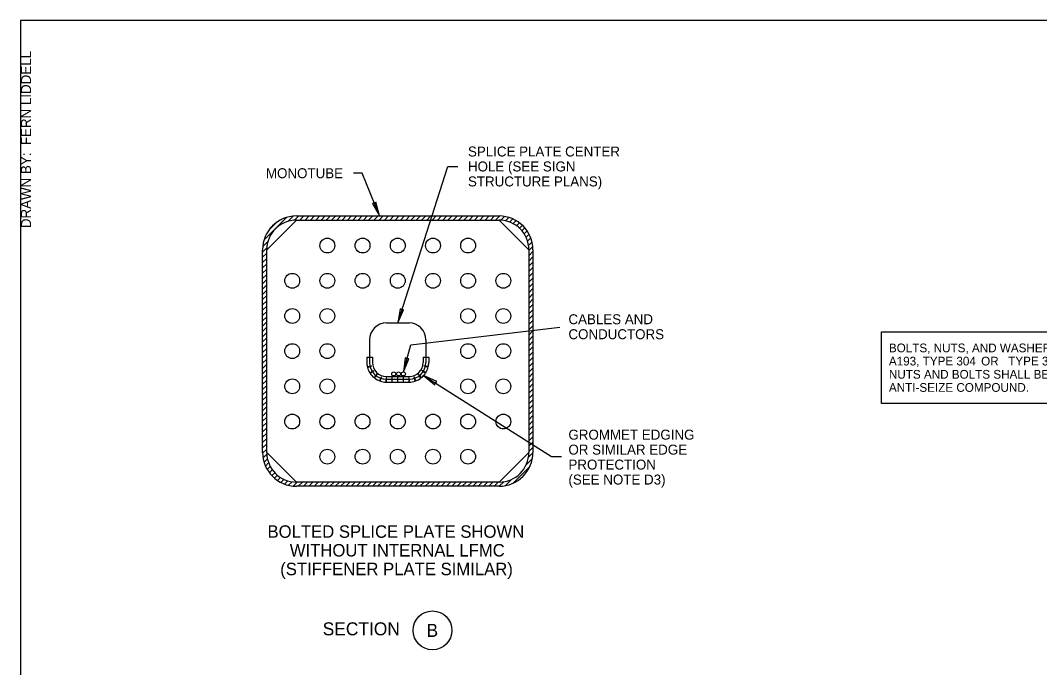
# Model space of a CAD drawing. Extents: x 99862 to 103680, y 99470 to 105076.
# Drawn here: x 99862 to 101496, y 104038 to 105076 of the extents above; entities that cross this region are included whole.
import ezdxf

# ---------------------------------------------------------------- set-up
doc = ezdxf.new("R2010")
doc.units = 0
for name, color, linetype in [('Level 1', 7, 'Continuous'), ('Level 12', 7, 'Continuous'), ('Level 15', 7, 'Continuous'), ('Level 2', 7, 'Continuous'), ('Level 20', 7, 'Continuous'), ('Level 3', 7, 'Continuous'), ('Level 62', 7, 'Continuous'), ('Level 9', 7, 'Continuous')]:
    doc.layers.add(name, color=color, linetype=linetype)

msp = doc.modelspace()

# ---------------------------------------------------------------- linework, layer by layer
at = {"layer": 'Level 1'}
msp.add_lwpolyline([(99862, 102999.5), (103151, 102999.5), (103151, 105075.5), (99862, 105075.5)], close=True, dxfattribs=at)
at = {"layer": 'Level 12'}
for p, q in [((100252.7, 104723.3), (100288.9, 104759.5)), ((100257, 104707.6), (100304.5, 104755.2)), ((100261.8, 104740.9), (100271.3, 104750.4)), ((100291.2, 104753.3), (100299.4, 104761.5)), ((100301.5, 104755.1), (100308.2, 104761.8)), ((100304.5, 104761.8), (100629.6, 104761.8)), ((100304.5, 104755.2), (100629.6, 104755.2)), ((100310.1, 104755.2), (100316.6, 104761.8)), ((100318.5, 104755.2), (100325.1, 104761.8)), ((100327, 104755.2), (100333.6, 104761.8)), ((100335.5, 104755.2), (100342.1, 104761.8)), ((100344, 104755.2), (100350.6, 104761.8)), ((100352.5, 104755.2), (100359.1, 104761.8)), ((100361, 104755.2), (100367.5, 104761.8)), ((100369.5, 104755.2), (100376, 104761.8)), ((100377.9, 104755.2), (100384.5, 104761.8)), ((100386.4, 104755.2), (100393, 104761.8)), ((100394.9, 104755.2), (100401.5, 104761.8)), ((100403.4, 104755.2), (100410, 104761.8)), ((100411.9, 104755.2), (100418.5, 104761.8)), ((100420.4, 104755.2), (100426.9, 104761.8)), ((100428.9, 104755.2), (100435.4, 104761.8)), ((100437.3, 104755.2), (100443.9, 104761.8)), ((100445.8, 104755.2), (100452.4, 104761.8)), ((100454.3, 104755.2), (100460.9, 104761.8)), ((100462.8, 104755.2), (100469.4, 104761.8)), ((100471.3, 104755.2), (100477.9, 104761.8)), ((100479.8, 104755.2), (100486.3, 104761.8)), ((100488.2, 104755.2), (100494.8, 104761.8)), ((100496.7, 104755.2), (100503.3, 104761.8)), ((100505.2, 104755.2), (100511.8, 104761.8)), ((100513.7, 104755.2), (100520.3, 104761.8)), ((100522.2, 104755.2), (100528.8, 104761.8)), ((100530.7, 104755.2), (100537.3, 104761.8)), ((100539.2, 104755.2), (100545.7, 104761.8)), ((100547.6, 104755.2), (100554.2, 104761.8)), ((100556.1, 104755.2), (100562.7, 104761.8)), ((100564.6, 104755.2), (100571.2, 104761.8)), ((100573.1, 104755.2), (100579.7, 104761.8)), ((100581.6, 104755.2), (100588.2, 104761.8)), ((100590.1, 104755.2), (100596.7, 104761.8)), ((100598.6, 104755.2), (100605.1, 104761.8)), ((100607, 104755.2), (100613.6, 104761.8)), ((100615.5, 104755.2), (100622.1, 104761.8)), ((100624, 104755.2), (100630.6, 104761.8)), ((100629.6, 104755.2), (100677.2, 104707.6)), ((100632.4, 104755.1), (100638.4, 104761.1)), ((100639.9, 104754.1), (100645.3, 104759.5)), ((100646.4, 104752.1), (100651.4, 104757.2)), ((100652.2, 104749.5), (100657.1, 104754.3)), ((100657.4, 104746.2), (100662.2, 104750.9)), ((100662.1, 104742.4), (100666.8, 104747)), ((100666.2, 104738), (100670.9, 104742.7)), ((100669.8, 104733.1), (100674.5, 104737.9)), ((100250.6, 104712.7), (100258.9, 104721)), ((100672.8, 104727.6), (100677.7, 104732.5)), ((100675.1, 104721.5), (100680.3, 104726.7)), ((100676.7, 104714.5), (100682.3, 104720.2)), ((100250.4, 104704), (100257, 104710.7)), ((100250.4, 104382.6), (100250.4, 104707.6)), ((100250.4, 104695.5), (100257, 104702.1)), ((100257, 104382.6), (100257, 104707.6)), ((100677.2, 104706.6), (100683.5, 104712.9)), ((100677.2, 104707.6), (100677.2, 104382.6)), ((100677.2, 104698.1), (100683.8, 104704.7)), ((100683.8, 104707.6), (100683.8, 104382.6)), ((100250.4, 104687), (100257, 104693.6)), ((100250.4, 104678.5), (100257, 104685.1)), ((100677.2, 104689.6), (100683.8, 104696.2)), ((100677.2, 104681.1), (100683.8, 104687.7)), ((100250.4, 104670.1), (100257, 104676.6)), ((100250.4, 104661.6), (100257, 104668.2)), ((100677.2, 104672.6), (100683.8, 104679.2)), ((100677.2, 104664.1), (100683.8, 104670.7)), ((100250.4, 104653.1), (100257, 104659.7)), ((100250.4, 104644.6), (100257, 104651.2)), ((100677.2, 104655.7), (100683.8, 104662.2)), ((100677.2, 104647.2), (100683.8, 104653.7)), ((100250.4, 104636.1), (100257, 104642.7)), ((100677.2, 104638.7), (100683.8, 104645.3)), ((100677.2, 104630.2), (100683.8, 104636.8)), ((100250.4, 104627.6), (100257, 104634.2)), ((100250.4, 104619.1), (100257, 104625.7)), ((100677.2, 104621.7), (100683.8, 104628.3)), ((100677.2, 104613.2), (100683.8, 104619.8)), ((100250.4, 104610.7), (100257, 104617.2)), ((100250.4, 104602.2), (100257, 104608.8)), ((100677.2, 104604.7), (100683.8, 104611.3)), ((100677.2, 104596.3), (100683.8, 104602.8)), ((100250.4, 104593.7), (100257, 104600.3)), ((100250.4, 104585.2), (100257, 104591.8)), ((100449, 104590.2), (100485.1, 104590.2)), ((100449, 104590.2), (100485.1, 104590.2)), ((100677.2, 104587.8), (100683.8, 104594.4)), ((100677.2, 104579.3), (100683.8, 104585.9)), ((100250.4, 104576.7), (100257, 104583.3)), ((100250.4, 104568.2), (100257, 104574.8)), ((100677.2, 104570.8), (100683.8, 104577.4)), ((100250.4, 104559.8), (100257, 104566.3)), ((100250.4, 104551.3), (100257, 104557.8)), ((100421.9, 104563.1), (100421.9, 104535.2)), ((100512.2, 104563.1), (100512.2, 104535.2)), ((100677.2, 104562.3), (100683.8, 104568.9)), ((100677.2, 104553.8), (100683.8, 104560.4)), ((100250.4, 104542.8), (100257, 104549.4)), ((100250.4, 104534.3), (100257, 104540.9)), ((100677.2, 104545.3), (100683.8, 104551.9)), ((100677.2, 104536.9), (100683.8, 104543.4)), ((100250.4, 104525.8), (100257, 104532.4)), ((100250.4, 104517.3), (100257, 104523.9)), ((100421.9, 104535.2), (100421.9, 104527)), ((100512.2, 104535.2), (100512.2, 104527)), ((100677.2, 104528.4), (100683.8, 104535)), ((100677.2, 104519.9), (100683.8, 104526.5)), ((100250.4, 104508.8), (100257, 104515.4)), ((100250.4, 104500.4), (100257, 104506.9)), ((100677.2, 104511.4), (100683.8, 104518)), ((100677.2, 104502.9), (100683.8, 104509.5)), ((100250.4, 104491.9), (100257, 104498.4)), ((100250.4, 104483.4), (100257, 104490)), ((100449, 104499.9), (100485.1, 104499.9)), ((100677.2, 104494.4), (100683.8, 104501)), ((100677.2, 104485.9), (100683.8, 104492.5)), ((100250.4, 104474.9), (100257, 104481.5)), ((100250.4, 104466.4), (100257, 104473)), ((100677.2, 104477.5), (100683.8, 104484)), ((100677.2, 104469), (100683.8, 104475.6)), ((100250.4, 104457.9), (100257, 104464.5)), ((100250.4, 104449.4), (100257, 104456)), ((100677.2, 104460.5), (100683.8, 104467.1)), ((100677.2, 104452), (100683.8, 104458.6)), ((100250.4, 104441), (100257, 104447.5)), ((100250.4, 104432.5), (100257, 104439.1)), ((100677.2, 104443.5), (100683.8, 104450.1)), ((100677.2, 104435), (100683.8, 104441.6)), ((100250.4, 104424), (100257, 104430.6)), ((100677.2, 104426.5), (100683.8, 104433.1)), ((100677.2, 104418.1), (100683.8, 104424.6)), ((100250.4, 104415.5), (100257, 104422.1)), ((100250.4, 104407), (100257, 104413.6)), ((100677.2, 104409.6), (100683.8, 104416.2)), ((100677.2, 104401.1), (100683.8, 104407.7)), ((100250.4, 104398.5), (100257, 104405.1)), ((100250.4, 104390), (100257, 104396.6)), ((100677.2, 104392.6), (100683.8, 104399.2)), ((100677.2, 104384.1), (100683.8, 104390.7)), ((100250.4, 104381.6), (100257, 104388.1)), ((100251.1, 104373.8), (100257, 104379.7)), ((100304.5, 104335), (100257, 104382.6)), ((100677.2, 104382.6), (100629.6, 104335)), ((100676.6, 104375), (100683.8, 104382.2)), ((100252.7, 104366.9), (100258.1, 104372.3)), ((100255, 104360.7), (100260, 104365.7)), ((100257.8, 104355.1), (100262.7, 104359.9)), ((100651.6, 104333), (100679.1, 104360.6)), ((100673, 104362.9), (100682.9, 104372.9)), ((100261.2, 104350), (100265.9, 104354.7)), ((100265.1, 104345.4), (100269.8, 104350.1)), ((100269.5, 104341.3), (100274.1, 104345.9)), ((100274.3, 104337.6), (100279.1, 104342.4)), ((100279.6, 104334.4), (100284.5, 104339.4)), ((100285.5, 104331.8), (100290.7, 104337)), ((100292, 104329.9), (100297.6, 104335.5)), ((100299.3, 104328.6), (100305.6, 104335)), ((100629.6, 104335), (100304.5, 104335)), ((100629.6, 104328.4), (100304.5, 104328.4)), ((100307.5, 104328.4), (100314.1, 104335)), ((100316, 104328.4), (100322.6, 104335)), ((100324.5, 104328.4), (100331, 104335)), ((100333, 104328.4), (100339.5, 104335)), ((100341.4, 104328.4), (100348, 104335)), ((100349.9, 104328.4), (100356.5, 104335)), ((100358.4, 104328.4), (100365, 104335)), ((100366.9, 104328.4), (100373.5, 104335)), ((100375.4, 104328.4), (100382, 104335)), ((100383.9, 104328.4), (100390.4, 104335)), ((100392.3, 104328.4), (100398.9, 104335)), ((100400.8, 104328.4), (100407.4, 104335)), ((100409.3, 104328.4), (100415.9, 104335)), ((100417.8, 104328.4), (100424.4, 104335)), ((100426.3, 104328.4), (100432.9, 104335)), ((100434.8, 104328.4), (100441.4, 104335)), ((100443.3, 104328.4), (100449.8, 104335)), ((100451.7, 104328.4), (100458.3, 104335)), ((100460.2, 104328.4), (100466.8, 104335)), ((100468.7, 104328.4), (100475.3, 104335)), ((100477.2, 104328.4), (100483.8, 104335)), ((100485.7, 104328.4), (100492.3, 104335)), ((100494.2, 104328.4), (100500.8, 104335)), ((100502.7, 104328.4), (100509.2, 104335)), ((100511.1, 104328.4), (100517.7, 104335)), ((100519.6, 104328.4), (100526.2, 104335)), ((100528.1, 104328.4), (100534.7, 104335)), ((100536.6, 104328.4), (100543.2, 104335)), ((100545.1, 104328.4), (100551.7, 104335)), ((100553.6, 104328.4), (100560.1, 104335)), ((100562.1, 104328.4), (100568.6, 104335)), ((100570.5, 104328.4), (100577.1, 104335)), ((100579, 104328.4), (100585.6, 104335)), ((100587.5, 104328.4), (100594.1, 104335)), ((100596, 104328.4), (100602.6, 104335)), ((100604.5, 104328.4), (100611.1, 104335)), ((100613, 104328.4), (100619.5, 104335)), ((100621.5, 104328.4), (100628, 104335)), ((100629.9, 104328.4), (100637.1, 104335.6)), ((100639.3, 104329.3), (100649.2, 104339.2))]:
    msp.add_line(p, q, dxfattribs=at)
for centre in [(100354.2, 104714.4), (100410.6, 104714.4), (100467.1, 104714.4), (100523.5, 104714.4), (100579.9, 104714.4), (100297.8, 104657.9), (100354.2, 104657.9), (100410.6, 104657.9), (100467.1, 104657.9), (100523.5, 104657.9), (100579.9, 104657.9), (100636.4, 104657.9), (100297.8, 104601.5), (100354.2, 104601.5), (100579.9, 104601.5), (100636.4, 104601.5), (100297.8, 104545.1), (100354.2, 104545.1), (100579.9, 104545.1), (100636.4, 104545.1), (100297.8, 104488.6), (100354.2, 104488.6), (100579.9, 104488.6), (100636.4, 104488.6), (100297.8, 104432.2), (100354.2, 104432.2), (100410.6, 104432.2), (100467.1, 104432.2), (100523.5, 104432.2), (100579.9, 104432.2), (100636.4, 104432.2), (100354.2, 104375.8), (100410.6, 104375.8), (100467.1, 104375.8), (100523.5, 104375.8), (100579.9, 104375.8)]:
    msp.add_circle(centre, 11.9, dxfattribs=at)
for centre, radius, start, end in [((100304.5, 104707.6), 54.2, 90, 180), ((100304.5, 104707.6), 47.6, 90, 180), ((100629.6, 104707.6), 54.2, 0, 90), ((100629.6, 104707.6), 47.6, 0, 90), ((100449, 104563.1), 27.1, 90, 180), ((100485.1, 104563.1), 27.1, 0, 90), ((100449, 104527), 27.1, 180, 270), ((100485.1, 104527), 27.1, 270, 0), ((100304.5, 104382.6), 54.2, 180, 270), ((100304.5, 104382.6), 47.6, 180, 270), ((100629.6, 104382.6), 54.2, 270, 0), ((100629.6, 104382.6), 54.2, 270, 0), ((100629.6, 104382.6), 47.6, 270, 0)]:
    msp.add_arc(centre, radius, start, end, dxfattribs=at)
at = {"layer": 'Level 15'}
for points in [[(100467.1, 104590.2), (100547.6, 104841.2), (100563.6, 104841.2)], [(100437.9, 104761.8), (100410.1, 104830.4), (100396.1, 104830.4)], [(100476, 104511.7), (100487.8, 104555.3), (100726.7, 104583.4)], [(100508.5, 104505.8), (100713.8, 104376), (100729.8, 104376)]]:
    msp.add_lwpolyline(points, dxfattribs=at)
for points in [[(100437.9, 104761.8), (100432.1, 104784.1), (100429.7, 104782), (100426.6, 104781.8)], [(100467.1, 104590.2), (100476.5, 104611.2), (100473.3, 104611.1), (100470.8, 104613)], [(100476, 104511.7), (100484.8, 104532.9), (100481.7, 104532.7), (100479.1, 104534.5)], [(100508.5, 104505.8), (100526.4, 104491.2), (100527, 104494.3), (100529.5, 104496.3)]]:
    msp.add_lwpolyline(points, close=True, dxfattribs=at)
at = {"layer": 'Level 2'}
for p, q in [((100417.4, 104535.2), (100426.4, 104535.2)), ((100417.4, 104535.2), (100417.4, 104527)), ((100418.2, 104520.2), (100425.4, 104521.3)), ((100418.5, 104519), (100425.4, 104521.3)), ((100426.4, 104535.2), (100426.4, 104527)), ((100507.7, 104535.2), (100507.7, 104527)), ((100507.7, 104535.2), (100516.7, 104535.2)), ((100516, 104520.2), (100508.7, 104521.3)), ((100515.7, 104519), (100508.7, 104521.3)), ((100516.7, 104535.2), (100516.7, 104527)), ((100422.1, 104510.5), (100428.6, 104513.9)), ((100422.7, 104509.5), (100428.5, 104513.9)), ((100429, 104502.6), (100434, 104507.9)), ((100430, 104501.8), (100434, 104507.9)), ((100438.1, 104497.4), (100441.1, 104504.1)), ((100449, 104504.4), (100485.1, 104504.4)), ((100496.1, 104497.4), (100493.1, 104504.1)), ((100494.9, 104497), (100493.1, 104504.1)), ((100505.2, 104502.6), (100500.2, 104507.9)), ((100504.2, 104501.8), (100500.2, 104507.9)), ((100512.1, 104510.5), (100505.6, 104513.9)), ((100511.4, 104509.4), (100505.6, 104513.9)), ((100439.3, 104496.9), (100441.1, 104504)), ((100448.4, 104495.4), (100449, 104502.6)), ((100449, 104495.4), (100449, 104502.7)), ((100449, 104495.4), (100485.1, 104495.4)), ((100458, 104495.4), (100458, 104502.7)), ((100467.1, 104495.4), (100467.1, 104502.7)), ((100476.1, 104495.4), (100476.1, 104502.7)), ((100485.1, 104495.4), (100485.1, 104502.7)), ((100485.8, 104495.4), (100485.1, 104502.7))]:
    msp.add_line(p, q, dxfattribs=at)
for centre, radius, start, end in [((100449, 104527), 31.6, 180, 192.4472), ((100449, 104527), 22.6, 180, 270), ((100485.1, 104527), 22.6, 270, 360), ((100485.1, 104527), 31.6, 347.5528, 360), ((100449, 104527), 31.6, 194.7641, 211.5458), ((100449, 104527), 31.6, 213.7593, 230.6443), ((100485.1, 104527), 31.6, 309.3557, 326.1373), ((100485.1, 104527), 31.6, 328.4542, 345.2359), ((100449, 104527), 31.6, 232.9613, 249.7429), ((100449, 104527), 31.6, 252.0952, 268.851), ((100485.1, 104527), 31.6, 271.1585, 287.9401), ((100485.1, 104527), 31.6, 290.2571, 307.0387)]:
    msp.add_arc(centre, radius, start, end, dxfattribs=at)
at = {"layer": 'Level 20'}
msp.add_circle((100522.8, 104097.2), 31.2, dxfattribs=at)
at = {"layer": 'Level 3'}
for centre in [(100460.6, 104508.5), (100468.3, 104508.5), (100476, 104508.5)]:
    msp.add_circle(centre, 3.24, dxfattribs=at)
at = {"layer": 'Level 9'}
msp.add_lwpolyline([(101242.4, 104575.8), (101799.7, 104575.8), (101799.7, 104461.2), (101242.4, 104461.2)], close=True, dxfattribs=at)

# ---------------------------------------------------------------- texts
at = {"layer": 'Level 20'}
for s, height, p in [('SPLICE PLATE CENTER', 16, (100579.6, 104857.2)), ('HOLE (SEE SIGN', 16, (100579.6, 104833.2)), ('MONOTUBE', 16, (100255.7, 104822.4)), ('STRUCTURE PLANS)', 16, (100579.6, 104809.2)), ('BOLTS, NUTS, AND WASHERS SHALL BE ', 14, (101254.5, 104543.2)), ('A193, TYPE 304', 14, (101254.5, 104522.1)), (' OR ', 14, (101397.2, 104522.1)), ('TYPE 316 ', 14, (101445.8, 104522.1)), ('NUTS AND BOLTS SHALL BE LIBERALLY COATED WITH ', 14, (101254.5, 104500.9)), ('ANTI-SEIZE COMPOUND.', 14, (101254.5, 104479.8)), ('BOLTED SPLICE PLATE SHOWN', 20, (100258.2, 104245.7)), ('WITHOUT INTERNAL LFMC', 20, (100293.9, 104215.7)), ('(STIFFENER PLATE SIMILAR)', 20, (100278.6, 104185.7)), ('SECTION', 20.82, (100346.7, 104089.3)), ('B', 20.8, (100513.2, 104086.8))]:
    msp.add_text(s, height=height, dxfattribs=at).set_placement(p)
for s, p in [('CABLES AND', (100740.7, 104588.2)), ('CONDUCTORS', (100740.7, 104564.2)), ('GROMMET EDGING', (100740.7, 104403.1)), ('OR SIMILAR EDGE', (100740.7, 104379.1)), ('PROTECTION', (100740.7, 104355.1)), ('(SEE NOTE D3)', (100740.7, 104331.1))]:
    msp.add_text(s, height=16, rotation=360, dxfattribs=at).set_placement(p)
at = {"layer": 'Level 62'}
msp.add_text('DRAWN BY:  FERN LIDDELL', height=16, rotation=90, dxfattribs=at).set_placement((99879, 104742.3))

doc.saveas('drawing.dxf')
